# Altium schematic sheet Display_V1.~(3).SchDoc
size A4; SheetNumber: 3; SheetTotal: 7
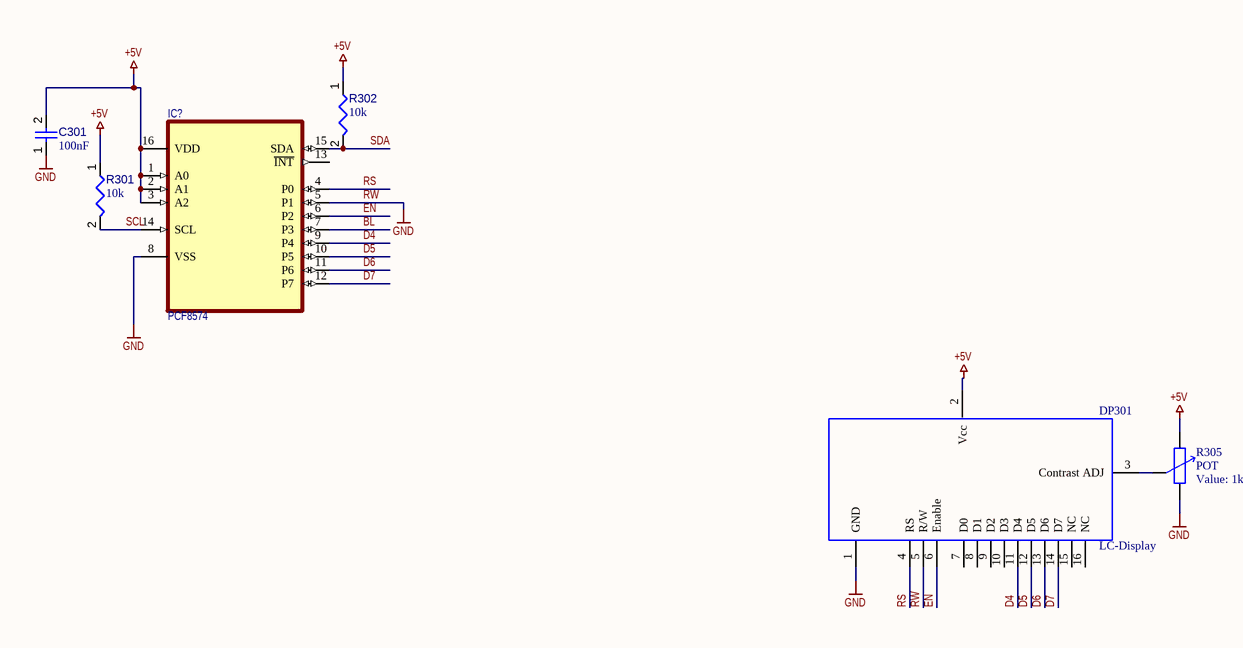
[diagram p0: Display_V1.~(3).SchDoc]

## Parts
C301  100nF  [CAPC1608X90X40NL10T20]
DP301  LC-Display  [V_THT_WM-C1610M]
IC?  PCF8574  [SO-16]
R301  10k  [RESC1608X55X25ML10T15]
R302  10k  [RESC1608X55X25ML10T15]
R305  POT  value 1k  [PT15]

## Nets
+5V: C301.2 DP301.2(Vcc) IC?.1(A0) IC?.2(A1) IC?.3(A2) IC?.16(VDD) R301.1 R302.1 R305.2
RW: C301.1 DP301.1(GND) DP301.5(R/W) IC?.5(P1) IC?.8(VSS) R305.1  [also labelled GND]
BL: IC?.7(P3)
D4: DP301.11(D4) IC?.9(P4)
D5: DP301.12(D5) IC?.10(P5)
D6: DP301.13(D6) IC?.11(P6)
D7: DP301.14(D7) IC?.12(P7)
EN: DP301.6(Enable) IC?.6(P2)
RS: DP301.4(RS) IC?.4(P0)
SCL: IC?.14(SCL) R301.2
SDA: IC?.15(SDA) R302.2
NetDP301_3: DP301.3(Contrast_ADJ) R305.3

Not connected (* = marked no-connect by the designer): DP301 7(D0) 8(D1) 9(D2) 10(D3) 15(NC) 16(NC); IC? 13(~{INT})

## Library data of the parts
C301 = CMP-001-00017-6: Chip Capacitor, 100 nF, +/- 10%, 50 V, 0603 (1608 Metric); Voltage Rating: 50V; Capacitor Type: Ceramic
DP301 = V_THT_LCD Modul: LCD
IC? = IC_PCF8574: I/O Expander
R301 R302 = CMP-009-00017-5: Chip Resistor, 10 KOhm, +/- 1%, 01 W, -55 to 155 degC, 0603 (1608 Metric); Voltage Rating: 50V; Power: 100mW
R305 = POT: Potentiometer; Set Position: 0.5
